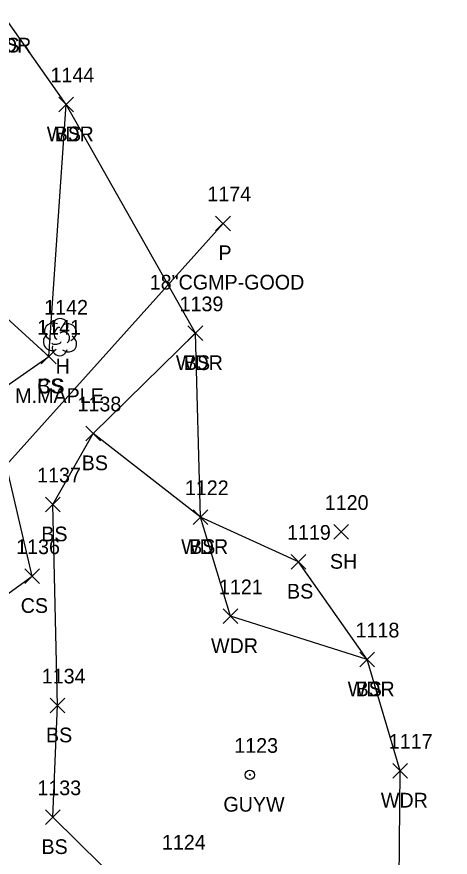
# Model space of a CAD drawing. Extents: x 1537342 to 1542195, y 163002 to 168596.
# Drawn here: x 1542030.9 to 1542089.8, y 163180.4 to 163294.7 of the extents above; entities that cross this region are included whole.
import ezdxf

# ---------------------------------------------------------------- set-up
doc = ezdxf.new("R2010")
doc.units = 0
for name, color, linetype in [('D_A', 7, 'Continuous'), ('D_C', 7, 'Continuous'), ('D_I', 7, 'Continuous'), ('D_TIC', 7, 'Continuous'), ('DCP', 7, 'Continuous'), ('L_A', 7, 'Continuous'), ('L_C', 7, 'Continuous'), ('L_I', 7, 'Continuous'), ('L_TIC', 7, 'Continuous'), ('LAWA', 7, 'Continuous'), ('LELB', 7, 'Continuous'), ('LTD', 7, 'Continuous'), ('U_A', 7, 'Continuous'), ('U_I', 7, 'Continuous'), ('UPGW', 7, 'Continuous')]:
    doc.layers.add(name, color=color, linetype=linetype)

msp = doc.modelspace()

# ---------------------------------------------------------------- linework, layer by layer
at = {"layer": 'D_TIC'}
for points in [[(1542057.96, 163265.56), (1542059.96, 163267.56)], [(1542059.96, 163265.56), (1542057.96, 163267.56)]]:
    msp.add_lwpolyline(points, dxfattribs=at)
at = {"layer": 'DCP'}
msp.add_lwpolyline([(1541974.93, 163172.92), (1542058.96, 163266.56)], dxfattribs=at)
at = {"layer": 'L_TIC'}
for points in [[(1542036.65, 163281.73), (1542038.65, 163283.73)], [(1542038.65, 163281.73), (1542036.65, 163283.73)], [(1542036.65, 163281.73), (1542038.65, 163283.73)], [(1542038.65, 163281.73), (1542036.65, 163283.73)], [(1542054.2, 163250.61), (1542056.2, 163252.61)], [(1542056.2, 163250.61), (1542054.2, 163252.61)], [(1542054.2, 163250.61), (1542056.2, 163252.61)], [(1542056.2, 163250.61), (1542054.2, 163252.61)], [(1542034.27, 163247.44), (1542036.27, 163249.44)], [(1542036.27, 163247.44), (1542034.27, 163249.44)], [(1542034.27, 163247.44), (1542036.27, 163249.44)], [(1542036.27, 163247.44), (1542034.27, 163249.44)], [(1542040.31, 163236.99), (1542042.31, 163238.99)], [(1542042.31, 163236.99), (1542040.31, 163238.99)], [(1542040.31, 163236.99), (1542042.31, 163238.99)], [(1542042.31, 163236.99), (1542040.31, 163238.99)], [(1542034.82, 163227.32), (1542036.82, 163229.32)], [(1542036.82, 163227.32), (1542034.82, 163229.32)], [(1542054.91, 163225.6), (1542056.91, 163227.6)], [(1542056.91, 163225.6), (1542054.91, 163227.6)], [(1542054.91, 163225.6), (1542056.91, 163227.6)], [(1542056.91, 163225.6), (1542054.91, 163227.6)], [(1542074, 163223.59), (1542076, 163225.59)], [(1542076, 163223.59), (1542074, 163225.59)], [(1542068.22, 163219.53), (1542070.22, 163221.53)], [(1542070.22, 163219.53), (1542068.22, 163221.53)], [(1542032.03, 163217.58), (1542034.03, 163219.58)], [(1542034.03, 163217.58), (1542032.03, 163219.58)], [(1542058.97, 163212.12), (1542060.97, 163214.12)], [(1542060.97, 163212.12), (1542058.97, 163214.12)], [(1542077.54, 163206.24), (1542079.54, 163208.24)], [(1542079.54, 163206.24), (1542077.54, 163208.24)], [(1542077.54, 163206.24), (1542079.54, 163208.24)], [(1542079.54, 163206.24), (1542077.54, 163208.24)], [(1542035.46, 163199.98), (1542037.46, 163201.98)], [(1542037.46, 163199.98), (1542035.46, 163201.98)], [(1542082.05, 163191.11), (1542084.05, 163193.11)], [(1542084.05, 163191.11), (1542082.05, 163193.11)], [(1542034.85, 163184.79), (1542036.85, 163186.79)], [(1542036.85, 163184.79), (1542034.85, 163186.79)]]:
    msp.add_lwpolyline(points, dxfattribs=at)
at = {"layer": 'LAWA'}
msp.add_lwpolyline([(1542191.37, 163069.26), (1542155.13, 163097.46), (1542123.95, 163126.28), (1542083.78, 163159.16), (1542082.85, 163172.31), (1542083.05, 163192.11), (1542078.54, 163207.24), (1542059.97, 163213.12), (1542055.91, 163226.6), (1542055.2, 163251.61), (1542037.65, 163282.73), (1542029.16, 163294.8)], dxfattribs=at)
at = {"layer": 'LELB'}
for points in [[(1542027.3, 163242.93), (1542035.27, 163248.44), (1542016.36, 163265.74), (1542014.6, 163273.95), (1542021.5, 163283.96), (1542029.16, 163294.8)], [(1542035.27, 163248.44), (1542037.65, 163282.73)], [(1542019.33, 163189.82), (1542022, 163197.12), (1542023.92, 163212.01), (1542033.03, 163218.58), (1542027.3, 163242.93), (1542014.56, 163249.2), (1542000.05, 163261.94), (1541997.36, 163271.88)], [(1542078.54, 163207.24), (1542069.22, 163220.53), (1542055.91, 163226.6), (1542041.31, 163237.99), (1542055.2, 163251.61)], [(1542185.24, 163058.1), (1542149.16, 163088.42), (1542116.16, 163116.47), (1542076.56, 163151.51), (1542049.16, 163172.67), (1542035.85, 163185.79), (1542036.46, 163200.98), (1542035.82, 163228.32), (1542041.31, 163237.99)]]:
    msp.add_lwpolyline(points, dxfattribs=at)
at = {"layer": 'LTD'}
msp.add_line((1542036.79, 163251.14), (1542036.79, 163251.14), dxfattribs=at)
msp.add_line((1542036.79, 163251.14), (1542036.79, 163251.14), dxfattribs=at)
msp.add_arc((1542036.83, 163252.57), 1.05, 335.5272, 180.9563, dxfattribs=at)
for centre, major_axis, ratio, start_param, end_param in [((1542035.99, 163251.8), (1.21, -0.51), 0.895232, 1.570796, 4.712389), ((1542037.83, 163251.72), (-1.14, -0.48), 0.949671, 1.570796, 4.712389), ((1542036.58, 163251.6), (-0.208, -0.792), 0.645439, 3.141593, 6.283185), ((1542035.7, 163250.43), (0.58, -1.04), 0.959034, 3.141593, 6.283185), ((1542037.29, 163250.97), (-0.5, 0.667), 0.989748, 3.141593, 6.283185), ((1542037.79, 163250.3), (-1.09, 0.79), 0.841452, 1.570796, 4.712389), ((1542036.79, 163249.64), (0.26, 1.06), 0.942809, 1.570796, 4.712389), ((1542036.33, 163250.39), (-0.625, -0.083), 0.423636, 0, 3.141593)]:
    msp.add_ellipse(centre, major_axis=major_axis, ratio=ratio, start_param=start_param, end_param=end_param, dxfattribs=at)
at = {"layer": 'UPGW'}
for radius in [0.625, 0.0833]:
    msp.add_circle((1542062.61, 163191.55), radius, dxfattribs=at)

# ---------------------------------------------------------------- texts
at = {"layer": 'D_A'}
msp.add_text('P', height=2, dxfattribs=at).set_placement((1542058.34, 163261.56))
at = {"layer": 'D_C'}
msp.add_text('18"CGMP-GOOD', height=2, dxfattribs=at).set_placement((1542049, 163257.56))
at = {"layer": 'D_I'}
msp.add_text('1174', height=2, dxfattribs=at).set_placement((1542056.83, 163269.56))
at = {"layer": 'L_A'}
for s, p in [('WDR', (1542026.52, 163289.8)), ('CS', (1542027.6, 163289.8)), ('WDR', (1542035.01, 163277.73)), ('BS', (1542036.09, 163277.73)), ('WDR', (1542052.56, 163246.61)), ('BS', (1542053.64, 163246.61)), ('H', (1542036.22, 163246.14)), ('CS', (1542033.71, 163243.44)), ('BS', (1542033.71, 163243.44)), ('BS', (1542039.76, 163232.99)), ('BS', (1542039.76, 163232.99)), ('BS', (1542034.26, 163223.32)), ('WDR', (1542053.27, 163221.6)), ('BS', (1542054.35, 163221.6)), ('SH', (1542073.49, 163219.59)), ('BS', (1542067.66, 163215.53)), ('CS', (1542031.47, 163213.58)), ('WDR', (1542057.33, 163208.12)), ('WDR', (1542075.9, 163202.24)), ('BS', (1542076.98, 163202.24)), ('BS', (1542034.9, 163195.98)), ('WDR', (1542080.41, 163187.11)), ('BS', (1542034.29, 163180.79))]:
    msp.add_text(s, height=2, dxfattribs=at).set_placement(p)
at = {"layer": 'L_C'}
msp.add_text('M.MAPLE', height=2, dxfattribs=at).set_placement((1542030.72, 163242.14))
at = {"layer": 'L_I'}
for s, p in [('1144', (1542035.52, 163285.73)), ('1144', (1542035.52, 163285.73)), ('1139', (1542053.06, 163254.61)), ('1139', (1542053.06, 163254.61)), ('1142', (1542034.66, 163254.14)), ('1141', (1542033.71, 163251.44)), ('1141', (1542033.71, 163251.44)), ('1138', (1542039.19, 163240.99)), ('1138', (1542039.19, 163240.99)), ('1137', (1542033.7, 163231.32)), ('1122', (1542053.78, 163229.6)), ('1122', (1542053.78, 163229.6)), ('1120', (1542072.79, 163227.59)), ('1119', (1542067.66, 163223.53)), ('1136', (1542030.85, 163221.58)), ('1121', (1542058.41, 163216.12)), ('1118', (1542076.98, 163210.24)), ('1118', (1542076.98, 163210.24)), ('1134', (1542034.33, 163203.98)), ('1117', (1542081.49, 163195.11)), ('1133', (1542033.73, 163188.79))]:
    msp.add_text(s, height=2, dxfattribs=at).set_placement(p)
at = {"layer": 'U_A'}
msp.add_text('GUYW', height=2, dxfattribs=at).set_placement((1542059.01, 163186.55))
at = {"layer": 'U_I'}
for s, p in [('1123', (1542060.49, 163194.55)), ('1124', (1542050.66, 163181.39))]:
    msp.add_text(s, height=2, dxfattribs=at).set_placement(p)

doc.saveas('drawing.dxf')
